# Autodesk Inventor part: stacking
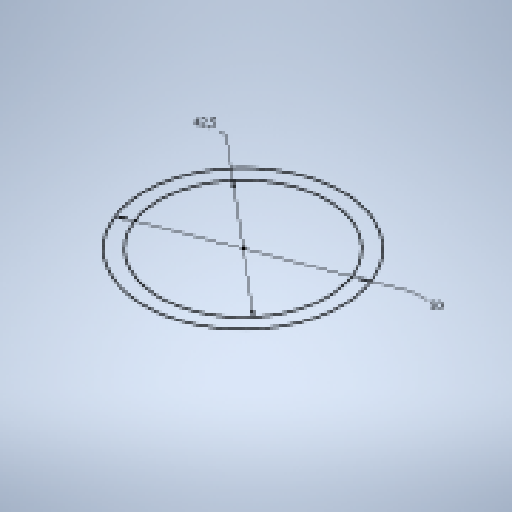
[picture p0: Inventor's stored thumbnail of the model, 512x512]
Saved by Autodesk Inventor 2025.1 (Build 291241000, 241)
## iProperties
Created: 2024-12
Part Number: stacking
Material: Generic
Document SubType Name: Modeling
Designer: mansa
Density: 1 g/cm^3
Appearance: Default
Author: mansa
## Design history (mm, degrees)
sketch "Sketch1"
  geometry: C1 r 21.25 at (0, 0); C2 r 25 at (0, 0); 1 further point
  constraints: 2 centre point, 2 coincident
  dimensions: "d0" = 42.5 diameter of C1; "d1" = 50 diameter of C2
extrude "Extrusion1" new body sketch "Sketch1" distance "d2" = 100; taper "d3" = 0 deg
sketch "Sketch2"
  geometry: C1 r 20.5 at (0, 0); 1 further point
  constraints: 1 centre point, 1 coincident
  dimensions: "d4" = 41 diameter of C1
extrude "Extrusion2" cut sketch "Sketch2" distance "d5" = 40; taper "d6" = 0 deg
body "Solid1"
